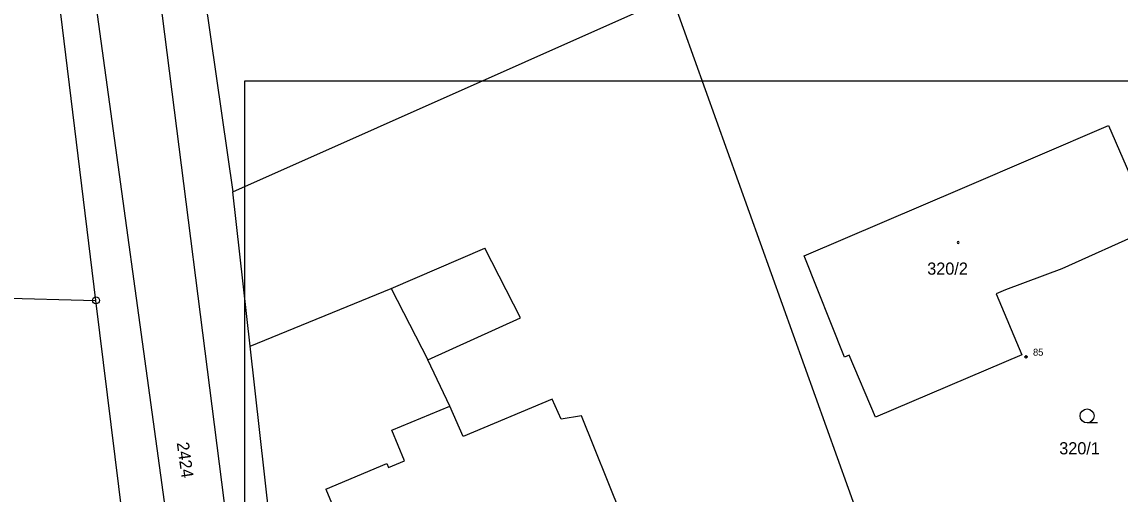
# Model space of a CAD drawing. Extents: x -454285 to -453563, y -1108687 to -1108249.
# Drawn here: x -454141.3 to -454078.1, y -1108528.5 to -1108501.4 of the extents above; entities that cross this region are included whole.
import ezdxf

# ---------------------------------------------------------------- set-up
doc = ezdxf.new("R2010")
doc.units = 0
for name, color, linetype in [('1', 7, 'Continuous'), ('14', 7, 'Continuous'), ('15', 7, 'Continuous'), ('16', 7, 'Continuous'), ('2', 7, 'Continuous'), ('23', 7, 'Continuous'), ('25', 7, 'Continuous'), ('28', 7, 'Continuous'), ('BODY_T1_2018', 7, 'Continuous'), ('CISLA_T1_2018', 7, 'Continuous'), ('rámy', 7, 'Continuous')]:
    doc.layers.add(name, color=color, linetype=linetype)

# ---------------------------------------------------------------- blocks, each defined once
blk = doc.blocks.new('Z402')
for start, end in [(0, 180), (180, 0)]:
    blk.add_arc((0, 0), 0.15, start, end)
blk = doc.blocks.new('Z105')
for radius in [0.5, 0.01]:
    blk.add_circle((0, 0), radius)
blk = doc.blocks.new('Z3040')
blk.add_line((1.5, 0), (0, 0))
blk.add_circle((0, 1), 1)
blk = doc.blocks.new('POINT_DISPLAY')
for p, q in [((-0.1, 0), (0.1, 0)), ((0, -0.1), (0, 0.1))]:
    blk.add_line(p, q)
blk.add_circle((0, 0), 0.05)
blk = doc.blocks.new('t1_2018')
at = {"layer": 'BODY_T1_2018'}
blk.add_blockref('POINT_DISPLAY', (-454083.5, -1108520.63), dxfattribs=at)
at = {"layer": 'CISLA_T1_2018'}
blk.add_text('85', height=0.4, dxfattribs=at).set_placement((-454083.1, -1108520.57))

msp = doc.modelspace()

# ---------------------------------------------------------------- linework, layer by layer
at = {"layer": '1'}
for p, q in [((-454137.067, -1108517.391), (-454142.337, -1108474.561)), ((-454134.187, -1108476.441), (-454129.187, -1108511.151)), ((-454129.187, -1108511.151), (-454103.897, -1108499.911)), ((-454103.897, -1108499.911), (-454091.257, -1108535.081)), ((-454087.157, -1108510.941), (-454078.747, -1108507.331)), ((-454078.747, -1108507.331), (-454076.207, -1108513.221)), ((-454128.187, -1108520.021), (-454129.187, -1108511.151)), ((-454096.277, -1108514.821), (-454087.157, -1108510.941)), ((-454076.207, -1108513.221), (-454081.447, -1108515.581)), ((-454120.057, -1108516.701), (-454114.677, -1108514.381)), ((-454112.607, -1108518.401), (-454114.677, -1108514.381)), ((-454093.957, -1108520.661), (-454096.277, -1108514.821)), ((-454081.447, -1108515.581), (-454084.677, -1108516.781)), ((-454188.527, -1108516.121), (-454137.067, -1108517.391)), ((-454128.187, -1108520.021), (-454120.057, -1108516.701)), ((-454084.677, -1108516.781), (-454085.227, -1108517.011)), ((-454133.677, -1108544.981), (-454137.067, -1108517.391)), ((-454085.227, -1108517.011), (-454083.737, -1108520.521)), ((-454117.947, -1108520.811), (-454112.607, -1108518.401)), ((-454126.827, -1108532.041), (-454128.187, -1108520.021)), ((-454093.687, -1108520.541), (-454093.957, -1108520.661)), ((-454092.167, -1108524.101), (-454093.687, -1108520.541)), ((-454083.737, -1108520.521), (-454092.167, -1108524.101)), ((-454116.687, -1108523.471), (-454117.947, -1108520.811)), ((-454110.797, -1108523.061), (-454115.917, -1108525.221)), ((-454110.267, -1108524.221), (-454110.797, -1108523.061)), ((-454115.917, -1108525.221), (-454116.687, -1108523.471)), ((-454109.107, -1108524.021), (-454110.267, -1108524.221)), ((-454106.827, -1108529.711), (-454109.107, -1108524.021))]:
    msp.add_line(p, q, dxfattribs=at)
at = {"layer": '2'}
for p, q in [((-454136.867, -1108472.781), (-454127.047, -1108549.571)), ((-454130.207, -1108549.991), (-454140.737, -1108473.691)), ((-454120.057, -1108516.701), (-454117.947, -1108520.811)), ((-454120.017, -1108524.861), (-454116.687, -1108523.471)), ((-454119.297, -1108526.611), (-454120.017, -1108524.861)), ((-454123.827, -1108528.241), (-454120.307, -1108526.761)), ((-454120.307, -1108526.761), (-454120.217, -1108526.991)), ((-454120.217, -1108526.991), (-454119.297, -1108526.611)), ((-454123.827, -1108528.241), (-454122.957, -1108530.341))]:
    msp.add_line(p, q, dxfattribs=at)
at = {"layer": 'rámy'}
msp.add_lwpolyline([(-454128.499, -1108504.754), (-454029.331, -1108504.754), (-454029.331, -1108564.805), (-454128.499, -1108564.805)], close=True, dxfattribs=at)

# ---------------------------------------------------------------- block references
msp.add_blockref('t1_2018', (0, 0))
at = {"layer": '23', "xscale": 0.4, "yscale": 0.4000000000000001}
msp.add_blockref('Z3040', (-454079.987, -1108524.434), dxfattribs=at)
at = {"layer": '25', "xscale": 0.4, "yscale": 0.4000000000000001}
msp.add_blockref('Z402', (-454087.415, -1108514.055), dxfattribs=at)
at = {"layer": '28', "xscale": 0.4, "yscale": 0.4000000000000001}
msp.add_blockref('Z105', (-454137.067, -1108517.391), dxfattribs=at)

# ---------------------------------------------------------------- texts
at = {"layer": '14'}
msp.add_text('320/1', height=0.7, dxfattribs=at).set_placement((-454081.589, -1108526.244))
at = {"layer": '15'}
msp.add_text('320/2', height=0.7, dxfattribs=at).set_placement((-454089.192, -1108515.911))
at = {"layer": '16'}
msp.add_text('2424', height=0.7, rotation=278.055, dxfattribs=at).set_placement((-454132.417, -1108525.581))

doc.saveas('drawing.dxf')
